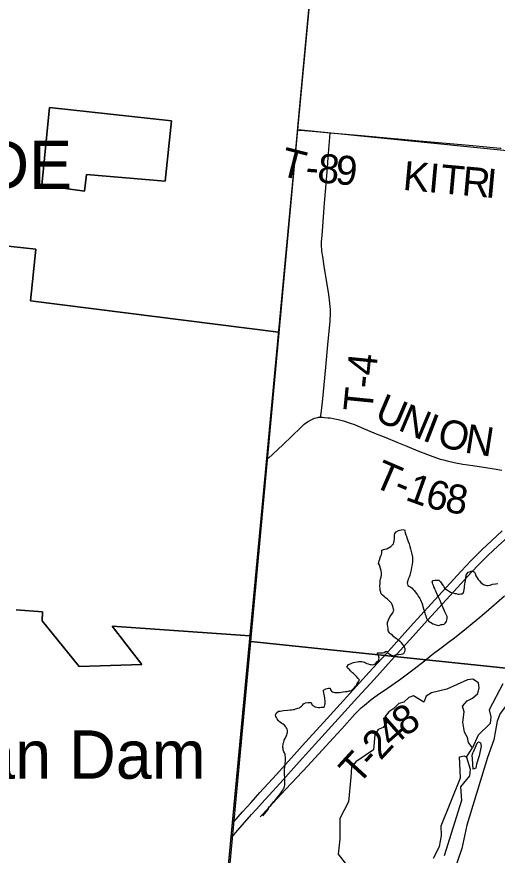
# Model space of a CAD drawing. Extents: x 1410790 to 1770854, y 448063 to 770588.
# Drawn here: x 1517806 to 1522773, y 660708 to 669381 of the extents above; entities that cross this region are included whole.
import ezdxf

# ---------------------------------------------------------------- set-up
doc = ezdxf.new("R2010")
doc.units = 0
for name, color, linetype in [('GM_X_Adjacent_County', 7, 'Continuous'), ('GM_X_Corporation', 7, 'Continuous'), ('GM_X_Corporation_Text', 7, 'Continuous'), ('GM_X_County', 7, 'Continuous'), ('GM_X_Hydro_Text', 7, 'Continuous'), ('GM_X_Major_River', 7, 'Continuous'), ('GM_X_Minor_Lake', 7, 'Continuous'), ('GM_X_Minor_River', 7, 'Continuous'), ('GM_X_Section', 7, 'Continuous'), ('GM_X_State_Route', 7, 'Continuous'), ('GM_X_Township', 7, 'Continuous'), ('GM_X_Township_Road', 7, 'Continuous'), ('GM_X_Township_Road_Text', 7, 'Continuous')]:
    doc.layers.add(name, color=color, linetype=linetype)

msp = doc.modelspace()

# ---------------------------------------------------------------- linework, layer by layer
at = {"layer": 'GM_X_Adjacent_County'}
msp.add_lwpolyline([(1521201.8, 673511.2), (1520708.9, 668234.8), (1520705, 668192.8), (1520384.1, 664777), (1520023.3, 660938), (1519813.3, 658702.6), (1519702.8, 657525.8), (1519766.8, 657522.5), (1519720.6, 657004.8), (1519314.6, 652452.1), (1519006.1, 648972.3), (1518813, 646827.1), (1518591.2, 644339.7)], dxfattribs=at)
at = {"layer": 'GM_X_Corporation'}
for points in [[(1516994.1, 673192.3), (1518538.2, 673057.3), (1518610.7, 673693.5), (1521196.8, 673431.2), (1520510.1, 666117.9), (1517946.6, 666444), (1518002.8, 666979.1), (1517488.2, 667033.2)], [(1517488.2, 667033.2), (1518002.8, 666979.1), (1517946.6, 666444), (1520510.1, 666117.9), (1520215.1, 662978.8), (1518790.4, 663078.1), (1519099.7, 662681.7), (1518450.1, 662659), (1518067.9, 663131.6), (1518072.9, 663226.6), (1517798.5, 663245.7)], [(1517798.5, 663245.7), (1518072.9, 663226.6), (1518067.9, 663131.6), (1518450.1, 662659), (1519099.7, 662681.7), (1518790.4, 663078.1), (1520215.1, 662978.8), (1519702.8, 657525.8), (1519766.8, 657522.5), (1519754.2, 657381), (1510021.6, 653053.7)]]:
    msp.add_lwpolyline(points, dxfattribs=at)
for points in [[(1518144.2, 668442.8), (1518064.7, 667638.8), (1518505.6, 667577.7), (1518526.3, 667748.6), (1519341.2, 667679.6), (1519403.9, 668303.6)], [(1518144.2, 668442.8), (1519403.9, 668303.6), (1519341.2, 667679.6), (1518526.3, 667748.6), (1518505.6, 667577.7), (1518064.7, 667638.8)]]:
    msp.add_lwpolyline(points, close=True, dxfattribs=at)
at = {"layer": 'GM_X_County'}
msp.add_lwpolyline([(1521201.8, 673511.2), (1520708.9, 668234.8), (1520705, 668192.8), (1520384.1, 664777), (1520023.3, 660938), (1519813.3, 658702.6), (1519702.8, 657525.8), (1519766.8, 657522.5), (1519720.6, 657004.8), (1519314.6, 652452.1), (1519006.1, 648972.3), (1518813, 646827.1), (1518591.2, 644339.7)], dxfattribs=at)
at = {"layer": 'GM_X_Major_River'}
for points in [[(1523190.7, 662656.2), (1523092.5, 662557.9), (1522804.3, 662172.8), (1522772.2, 662095.5), (1522737.2, 661902.1), (1522672.5, 661719.4), (1522458.3, 661019.9), (1522408, 660776.8), (1522321.4, 660524.6)], [(1522830.2, 662482.7), (1522689.1, 662212), (1522705.3, 662141.4), (1522699.5, 662069.4), (1522574.3, 661950.5), (1522516.3, 661820.1)], [(1522561.2, 661863.3), (1522579.6, 661881), (1522601.5, 661872.5), (1522606.8, 661836.3), (1522584.7, 661736.4), (1522558.9, 661648.7), (1522552.1, 661608.7), (1522523.9, 661599.2), (1522520.9, 661651.5), (1522516, 661705.7), (1522512.7, 661741.9), (1522523.4, 661775.8)], [(1522561.2, 661863.3), (1522523.4, 661775.8)], [(1522454.3, 661723.3), (1522516.3, 661820.1)], [(1522454.3, 661723.3), (1522493.2, 661600), (1522487.3, 661528), (1522394.3, 661414.3), (1522402.7, 661273.8), (1522225.9, 660703.5)]]:
    msp.add_lwpolyline(points, dxfattribs=at)
at = {"layer": 'GM_X_Minor_Lake'}
for points in [[(1522516.3, 661820.1), (1522475.3, 661873.1), (1522466.4, 661927.5), (1522435.4, 661980.2), (1522417.5, 662084.9), (1522431.7, 662193), (1522412.8, 662251.6), (1522462, 662306.8), (1522518.6, 662333.7), (1522571.7, 662382.8), (1522586.8, 662438.7), (1522577.9, 662493), (1522520.6, 662530.3), (1522466.4, 662523.4), (1522252.1, 662427.4), (1522093.1, 662388.5), (1522038.3, 662353.5), (1522015, 662291.8), (1521908.2, 662356.1), (1521857.8, 662339.1), (1521806.7, 662292), (1521756.4, 662278.9), (1521705.2, 662225.8), (1521652.5, 662192.8), (1521611.4, 662139.4), (1521632.2, 662080.8), (1521593.1, 662029.4), (1521542.6, 662008.4), (1521507.5, 661954.9), (1521492.3, 661798.7), (1521311.6, 661675.9), (1521266.4, 661620.7), (1521261.3, 661564.6), (1521260.3, 661514.5), (1521237.1, 661260.1), (1521145.5, 661087.4), (1521147.2, 660874.8), (1521130.1, 660718.6), (1521214, 660610.6)], [(1522454.3, 661723.3), (1522516.3, 661820.1)], [(1522112.7, 660678.7), (1522177.2, 660797.8), (1522197.5, 660909.7), (1522193.6, 661012.1), (1522393.8, 661507.6), (1522382.2, 661726.5), (1522432.5, 661737.5), (1522454.3, 661723.3), (1522454.3, 661723.3)]]:
    msp.add_lwpolyline(points, dxfattribs=at)
at = {"layer": 'GM_X_Minor_River'}
for points in [[(1521639.4, 663090.8), (1521639.6, 663102.9), (1521639.8, 663114.9), (1521644.1, 663132.9), (1521652.4, 663152.9), (1521666.9, 663176.7), (1521681.2, 663198.6), (1521693.5, 663214.5), (1521704, 663242.4), (1521702.2, 663254.5), (1521698.5, 663272.6), (1521690.7, 663290.8), (1521681.1, 663315.1), (1521661.3, 663333.4), (1521647.5, 663347.7), (1521633.7, 663360), (1521617.8, 663370.3), (1521604, 663384.6), (1521588.2, 663398.9), (1521574.4, 663413.2), (1521568.7, 663429.3), (1521562.9, 663445.5), (1521561.2, 663465.6), (1521559.6, 663491.7), (1521562.1, 663521.8), (1521564.5, 663545.8), (1521566.8, 663565.9), (1521573.2, 663585.9), (1521575.5, 663607.9), (1521575.9, 663628), (1521572.2, 663650.1), (1521566.6, 663674.3), (1521558.9, 663698.5), (1521551.2, 663714.7), (1521547.3, 663724.8), (1521547.5, 663734.9), (1521551.8, 663752.9), (1521558.1, 663770.8), (1521564.4, 663788.8), (1521570.7, 663804.8), (1521574.9, 663820.8), (1521579.2, 663834.7), (1521579.3, 663844.8), (1521581.5, 663854.8), (1521581.6, 663864.8), (1521611.9, 663874.4), (1521632, 663878.1), (1521672.4, 663901.5), (1521690.8, 663919.3), (1521700.9, 663929.1), (1521705.2, 663943.1), (1521707.5, 663961.2), (1521709.8, 663981.2), (1521712.1, 664001.2), (1521712.4, 664021.3), (1521714.7, 664035.3), (1521729, 664055.2), (1521753.3, 664066.8), (1521779.4, 664074.4), (1521801.5, 664078.1), (1521815.5, 664075.9), (1521817.3, 664063.8), (1521821, 664043.6), (1521826.7, 664023.5), (1521834.5, 664007.3), (1521840.2, 663991.1), (1521846, 663973), (1521853.7, 663952.8), (1521861.3, 663928.5), (1521868.9, 663902.3), (1521876.5, 663876.1), (1521884.1, 663849.9), (1521889.7, 663823.7), (1521897.2, 663791.4), (1521898.8, 663767.3), (1521896.4, 663743.2), (1521894, 663715.2), (1521887.5, 663687.2), (1521883.1, 663661.1), (1521876.6, 663633.1), (1521868.1, 663605.2), (1521861.8, 663583.2), (1521853.4, 663563.2), (1521849.2, 663551.2), (1521842.8, 663527.3), (1521850.4, 663499), (1521860.3, 663490.8), (1521880.2, 663480.5), (1521892, 663470.2), (1521903.9, 663458), (1521915.7, 663445.8), (1521937.3, 663417.3), (1521947.1, 663403.1), (1521956.9, 663388.9), (1521972.5, 663362.5), (1521980.3, 663350.3), (1521986.1, 663334.2), (1521993.8, 663318), (1521999.6, 663299.8), (1522005.2, 663279.7), (1522010.9, 663257.5)], [(1522010.9, 663257.5), (1522016.6, 663239.3), (1522022.4, 663223.2), (1522026.2, 663211.1), (1522028, 663199), (1522033.8, 663184.8), (1522039.6, 663168.7), (1522049.2, 663148.4), (1522065, 663130.1), (1522078.9, 663119.8), (1522092.8, 663111.6), (1522108.7, 663103.3), (1522122.6, 663097.1), (1522138.6, 663092.8), (1522152.5, 663088.5), (1522162.5, 663086.4), (1522176.6, 663088.1), (1522194.7, 663093.9), (1522206.8, 663095.7), (1522222.8, 663099.4), (1522235, 663109.3), (1522247.4, 663127.2), (1522251.6, 663141.1), (1522253.9, 663161.2), (1522254.2, 663179.2), (1522232.9, 663227.8), (1522225.2, 663244), (1522215.5, 663268.2), (1522203.9, 663290.5), (1522194.3, 663316.7), (1522182.7, 663345), (1522171, 663369.3), (1522161.3, 663387.6), (1522153.6, 663403.7), (1522145.9, 663423.9), (1522138.1, 663440.1), (1522132.3, 663452.3), (1522126.5, 663466.4), (1522118.8, 663484.6), (1522113, 663498.8), (1522107.2, 663510.9), (1522103.4, 663525), (1522101.6, 663537.1), (1522109.8, 663549), (1522127.9, 663552.7), (1522152, 663554.4), (1522168, 663552.1), (1522177.9, 663547.9), (1522185.8, 663537.7), (1522193.6, 663525.6), (1522203.3, 663509.3), (1522217.1, 663491), (1522232.7, 663466.7), (1522258.5, 663450.2), (1522278.4, 663437.8), (1522296.2, 663427.5), (1522316.2, 663423.2), (1522334.2, 663416.9), (1522348.2, 663414.6), (1522366.1, 663410.3), (1522380.2, 663410.1), (1522396.2, 663411.8), (1522410.3, 663413.6), (1522420.4, 663417.5), (1522428.7, 663435.4), (1522431, 663455.4), (1522433.3, 663475.5), (1522435.6, 663491.5), (1522442.2, 663531.5), (1522444.5, 663549.6), (1522448.9, 663573.6), (1522453.4, 663603.7), (1522461.7, 663621.6), (1522474, 663635.4), (1522486.1, 663641.3), (1522502.2, 663647), (1522518.2, 663646.8), (1522528.2, 663644.6), (1522538.1, 663636.4), (1522543.9, 663622.3), (1522553.5, 663598), (1522565.2, 663577.7), (1522577, 663561.5), (1522588.8, 663545.2), (1522602.6, 663531), (1522618.4, 663520.7), (1522632.3, 663510.4), (1522650.2, 663502.1), (1522664.2, 663499.8), (1522680.2, 663499.6), (1522700.3, 663503.3), (1522722.5, 663510.9), (1522754.6, 663514.4), (1522778.8, 663520)], [(1520986.2, 662354.6), (1520982.5, 662370.7), (1520978.8, 662388.8), (1520977, 662402.9), (1520977.2, 662414.9), (1520999.5, 662430.7), (1521027.6, 662436.2), (1521045.7, 662435.9), (1521049.4, 662417.8), (1521059.2, 662405.6), (1521071.1, 662397.4), (1521089.1, 662393), (1521109.1, 662392.7), (1521129.2, 662392.4), (1521143.2, 662392.2), (1521159.2, 662393.9), (1521181.4, 662399.6), (1521205.5, 662401.2), (1521221.5, 662403), (1521241.7, 662408.7), (1521257.7, 662410.4), (1521267.8, 662412.2), (1521278, 662422.1), (1521286.1, 662432), (1521296.3, 662441.9), (1521308.6, 662455.8), (1521316.7, 662465.7), (1521322.9, 662477.6), (1521333.2, 662491.5), (1521341.5, 662507.4), (1521347.7, 662521.4), (1521335.9, 662537.6), (1521318.2, 662558), (1521302.4, 662574.3), (1521288.6, 662586.6), (1521276.7, 662596.8), (1521264.9, 662607), (1521255, 662617.2), (1521241.2, 662631.5), (1521231.3, 662639.7), (1521217.5, 662654), (1521236, 662681.8), (1521264.2, 662691.4), (1521278.3, 662697.2), (1521288.4, 662701), (1521324.7, 662710.5), (1521340.7, 662712.2), (1521358.8, 662711.9), (1521372.8, 662711.7), (1521386.8, 662709.5), (1521400.7, 662705.2), (1521412.7, 662699), (1521424.6, 662692.8), (1521438.6, 662688.5), (1521454.5, 662682.3), (1521470.5, 662680), (1521482.5, 662677.8), (1521498.6, 662681.5), (1521516.8, 662693.3), (1521529.1, 662709.2), (1521545.3, 662722.9), (1521553.7, 662746.9), (1521544.1, 662771.2), (1521536.4, 662791.4), (1521536.6, 662803.4), (1521558.7, 662803), (1521578.7, 662800.7), (1521594.7, 662800.4), (1521604.8, 662806.3), (1521619, 662814.1), (1521631, 662817.9), (1521638.8, 662803.8), (1521656.7, 662791.4), (1521674.6, 662781.1), (1521690.5, 662774.8), (1521702.5, 662772.6), (1521722.7, 662780.3), (1521752.8, 662785.8), (1521778.9, 662789.4), (1521797, 662791.1), (1521807.1, 662795), (1521817.4, 662814.9), (1521819.6, 662828.9), (1521819.9, 662845), (1521814.1, 662861.1), (1521806.4, 662875.3), (1521796.6, 662889.5), (1521782.8, 662903.8), (1521769, 662918.1), (1521753.1, 662930.4), (1521737.3, 662942.7), (1521721.4, 662953), (1521705.6, 662967.3), (1521691.8, 662983.6), (1521672, 662996), (1521662.1, 663004.2), (1521650.4, 663022.4), (1521646.5, 663032.5), (1521644.9, 663054.6), (1521641.2, 663074.8), (1521639.4, 663090.8)], [(1520351.1, 661116.2), (1520404.2, 661181.5), (1520410.6, 661201.5), (1520418.7, 661211.4), (1520431, 661223.3), (1520437.2, 661235.2), (1520449.4, 661247.1), (1520461.6, 661260.9), (1520475.9, 661276.8), (1520494.3, 661298.5), (1520508.6, 661314.4), (1520522.9, 661332.2), (1520535.2, 661350.1), (1520547.5, 661365.9), (1520555.7, 661379.8), (1520564, 661393.8), (1520570.2, 661405.7), (1520574.4, 661417.7), (1520576.6, 661433.7), (1520577.1, 661465.8), (1520575.5, 661489.9), (1520575.9, 661514), (1520574.3, 661540.1), (1520573.3, 661600.4), (1520577.6, 661620.4), (1520579.9, 661640.4), (1520582.3, 661660.5), (1520584.6, 661682.5), (1520582.9, 661702.6), (1520583.3, 661724.7), (1520581.5, 661738.8), (1520579.7, 661748.8), (1520573.9, 661767), (1520568.1, 661779.1), (1520564.3, 661789.2), (1520560.4, 661799.3), (1520558.6, 661811.4), (1520556.8, 661823.5), (1520557, 661837.5), (1520559.3, 661851.5), (1520561.5, 661863.6), (1520565.7, 661877.5), (1520572, 661897.5), (1520580.4, 661917.4), (1520588.6, 661931.4), (1520592.8, 661943.3), (1520597, 661955.3), (1520601.2, 661967.3), (1520603.4, 661977.3), (1520603.5, 661987.3), (1520605.7, 661997.3), (1520601.9, 662011.5), (1520596.1, 662023.6), (1520586.3, 662037.8), (1520572.5, 662054.1), (1520558.7, 662064.4), (1520546.8, 662072.6), (1520532.9, 662080.8), (1520517, 662093.1), (1520509.2, 662103.3), (1520499.4, 662119.5), (1520489.6, 662131.7), (1520483.8, 662143.9), (1520482, 662157.9), (1520484.1, 662167.9), (1520492.4, 662181.9), (1520512.7, 662197.6), (1520528.7, 662199.4), (1520562.9, 662206.8), (1520603.1, 662210.2), (1520631.2, 662211.8), (1520647.2, 662213.5), (1520663.3, 662215.2), (1520673.3, 662217.1), (1520691.5, 662222.8), (1520711.6, 662228.5), (1520727.7, 662234.3), (1520739.9, 662242.1), (1520750.1, 662252), (1520762.3, 662263.8), (1520770.5, 662273.7), (1520790.7, 662283.4), (1520816.8, 662289), (1520840.9, 662288.7), (1520850.9, 662288.5), (1520856.5, 662266.3), (1520868.4, 662256.1), (1520880.3, 662249.9), (1520892.2, 662241.7), (1520908.2, 662239.4), (1520924.2, 662237.1), (1520938.2, 662236.9), (1520952.3, 662238.7), (1520966.3, 662238.4), (1520976.4, 662240.3), (1520988.5, 662248.1), (1520990.8, 662262.1), (1520993, 662278.2), (1520993.3, 662294.2), (1520989.9, 662336.4), (1520986.2, 662354.6)]]:
    msp.add_lwpolyline(points, dxfattribs=at)
at = {"layer": 'GM_X_Section'}
for points in [[(1526036.5, 667680.5), (1525566.4, 662362), (1520227.3, 662918.2), (1520710.8, 668214.9)], [(1525566.4, 662362), (1525082.9, 657079.6), (1519790, 657541.4), (1519726.6, 657548), (1520227.3, 662918.2)]]:
    msp.add_lwpolyline(points, close=True, dxfattribs=at)
at = {"layer": 'GM_X_State_Route'}
for points in [[(1520033.5, 660900.2), (1520090.8, 660966), (1520232.8, 661129.4), (1520283.2, 661185.8), (1520335.6, 661244.5), (1520528.4, 661454.9), (1520726.2, 661674), (1520926.7, 661895.1), (1521331.6, 662342.5), (1521499.5, 662526.8), (1521675.8, 662721.2), (1522056, 663142.4), (1522323.6, 663435.5), (1522507.2, 663636.7), (1522584.3, 663717.4), (1522677.4, 663810), (1522782.5, 663909.2), (1522885.2, 664001.1), (1522998, 664096.7), (1523063.3, 664149.3)], [(1520049, 661055.2), (1520139.3, 661156.3), (1520228, 661254.6), (1520319.6, 661356), (1520490, 661542.5), (1520643.9, 661712.9), (1520789, 661873.6), (1520981.8, 662083.8), (1521285.1, 662419.8), (1521450.5, 662601.9), (1521620.3, 662788.9), (1521876.6, 663074.6), (1522090.9, 663309.8), (1522398.7, 663646.1), (1522504.7, 663757.8), (1522618.2, 663871.5), (1522713, 663962), (1522824.7, 664063.2)]]:
    msp.add_lwpolyline(points, dxfattribs=at)
at = {"layer": 'GM_X_Township'}
msp.add_lwpolyline([(1521201.8, 673511.2), (1520708.9, 668234.8), (1520705, 668192.8), (1520384.1, 664777), (1520023.3, 660938), (1519813.3, 658702.6), (1519702.8, 657525.8), (1519766.8, 657522.5), (1519720.6, 657004.8), (1519314.6, 652452.1), (1524688.8, 651910.7), (1526106.4, 651767.9), (1530096, 651366), (1531112.1, 651263.6), (1532044.4, 651169.7), (1532157.4, 651158.4), (1532426.7, 651131.2), (1533590, 651014), (1540632, 650304.6), (1541201.9, 650247.2), (1548862.1, 649478.6)], dxfattribs=at)
at = {"layer": 'GM_X_Township_Road'}
for points in [[(1520722.1, 668210.1), (1520744, 668208.2), (1520939.9, 668191), (1521045.2, 668181.6)], [(1520947.2, 665239.6), (1520949.2, 665258), (1520951.7, 665281.7), (1520959.1, 665334.9), (1520969.6, 665428.2), (1520983.2, 665573.6), (1521001.2, 665757.6), (1521023.2, 665989.4), (1521042.9, 666197.6), (1521045.5, 666229.2), (1521047.1, 666257.9), (1521049.1, 666293.7), (1521049.1, 666323.5), (1521048.4, 666353.2), (1521046.6, 666380.4), (1521043.5, 666418.8), (1521032.3, 666506.9), (1520985.4, 666801.9), (1520968.6, 666902.8), (1520960.9, 666957), (1520958.9, 666977.2), (1520957.2, 667005.7), (1520957, 667028.7), (1520957.6, 667054.5), (1520962.2, 667119.8), (1520988.1, 667454.3), (1521007.4, 667695.5), (1521011.1, 667741.1), (1521017.9, 667819.1), (1521026.4, 667926.2), (1521041.5, 668131.3), (1521045.2, 668181.6)], [(1521045.2, 668181.6), (1521211, 668166.7), (1521371, 668152.5), (1521746.6, 668117.8), (1521965.3, 668097.3), (1522086.2, 668087.1), (1522520.6, 668048.5), (1522804.8, 668023.8), (1522815.1, 668022.9)], [(1520404.6, 664811.8), (1520557.3, 664953.2), (1520742.2, 665132.8), (1520778.8, 665167.1), (1520813.1, 665192.5), (1520841.6, 665209.5), (1520868.9, 665222.5), (1520884.1, 665228.4), (1520900.6, 665233.4), (1520916.8, 665237.1), (1520926, 665238.3), (1520935.5, 665239.3), (1520947.2, 665239.6)], [(1520947.2, 665239.6), (1520948.2, 665239.6), (1520965.1, 665238.7), (1520987.5, 665237.1), (1521022.9, 665234.3), (1521044.4, 665231.5), (1521076.2, 665226.9), (1521128, 665216.5), (1521184.1, 665201.2), (1521252.8, 665178.6), (1521296, 665162.8), (1521365.6, 665134.2), (1521523.1, 665069), (1521620.1, 665028.9), (1521735, 664981.4), (1521838, 664938.7), (1521953.4, 664891.8), (1522105.9, 664832.1), (1522155.1, 664815), (1522184.6, 664806.4), (1522219, 664797.3), (1522256.5, 664788.7), (1522326.5, 664772.5), (1522416.5, 664755.2), (1522521.8, 664738.3), (1522721, 664708.2), (1522821.5, 664693)], [(1521467.7, 662316.8), (1521470.8, 662319.3), (1521531.2, 662364.8), (1521638, 662438.1), (1521763.9, 662523.4), (1521832, 662574.2), (1521915.9, 662637.6), (1522021.8, 662720.6), (1522101.8, 662783.3), (1522208.5, 662864.8), (1522270.3, 662911.4), (1522318.6, 662946.9), (1522419.2, 663024.4), (1522550.5, 663135.3), (1522657.7, 663226.8), (1522848.1, 663391.2)], [(1520322.8, 661106.6), (1520332.2, 661115.4), (1520343.1, 661126.2), (1520498.5, 661295.9), (1520589, 661390.8), (1520816.3, 661631.7), (1521077, 661917.8), (1521167.2, 662017.5), (1521301.2, 662166.1), (1521326.3, 662192.6), (1521349, 662215.4), (1521367.3, 662232.8), (1521399.2, 662262.2), (1521467.7, 662316.8)]]:
    msp.add_lwpolyline(points, dxfattribs=at)

# ---------------------------------------------------------------- texts
at = {"layer": 'GM_X_Corporation_Text'}
msp.add_text('RIVERSIDE', height=500, rotation=0.00001, dxfattribs=at).set_placement((1514775.1, 667601))
at = {"layer": 'GM_X_Hydro_Text'}
msp.add_text('Huffman Dam', height=499.993, rotation=0.00884, dxfattribs=at).set_placement((1515634, 661499.2))
at = {"layer": 'GM_X_Township_Road_Text'}
for s, rotation, p in [('T', 345.56358, (1520511.2, 667745)), ('8', 354.7733, (1520906.4, 667670.3)), ('9', 354.90932, (1521091.2, 667653.4)), ('K', 354.82025, (1521790.2, 667592)), ('I', 354.82491, (1522053.2, 667568.1)), ('T', 354.82012, (1522175.9, 667557)), ('R', 354.81759, (1522399.3, 667536.8)), ('-', 355.54309, (1520784.6, 667679.8)), ('I', 354.80981, (1522644.7, 667514.5)), ('T-4', 84.30235, (1521479.9, 665285.6)), ('U', 336.92338, (1521491.5, 665214.7)), ('N', 337.16866, (1521735.7, 665110.7)), ('I', 338.91074, (1521988.2, 665004.5)), ('O', 345.25292, (1522137.7, 664949.1)), ('N', 351.14621, (1522426, 664875)), ('T', 336.6824, (1521473.4, 664530)), ('1', 340.1679, (1521811.9, 664387.1)), ('-', 337.67114, (1521684.7, 664439)), ('6', 345.54866, (1522015.1, 664315.4)), ('8', 350.69243, (1522222.8, 664263.2)), ('8', 35.27361, (1521820, 661927.1)), ('4', 41.07259, (1521687, 661810.6)), ('2', 47.23604, (1521567.6, 661680.9)), ('T', 47.59038, (1521333.4, 661424.7)), ('-', 47.53702, (1521484.7, 661590.3))]:
    msp.add_text(s, height=300, rotation=rotation, dxfattribs=at).set_placement(p)

doc.saveas('drawing.dxf')
